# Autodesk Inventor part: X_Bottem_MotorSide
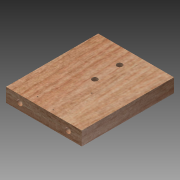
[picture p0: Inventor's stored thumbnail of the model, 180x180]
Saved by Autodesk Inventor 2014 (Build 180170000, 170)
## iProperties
Created: 2013-12
Part Number: X_Bottem_MotorSide
Material: Birch
Document SubType Name: Modeling
Designer: Bram
Density: 0.512 g/cm^3
Appearance: Birch - Natural Medium Gloss
Author: Bram
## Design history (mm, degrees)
sketch "Sketch1"
  geometry: L1 (0, 0)-(110, 0); L2 (110, 0)-(110, 20); L3 (110, 20)-(0, 20); L4 (0, 20)-(0, 0)
  constraints: 8 end point, 2 parallel, 1 horizontal, 1 perpendicular
  dimensions: "d0" = 110 distance of L3.end L2.end; "d1" = 20 distance of L2.end L1.end
extrude "Extrusion1" new body sketch "Sketch1" distance "d2" = 134; taper "d3" = 0 deg
sketch "Sketch2"
  geometry: L1 (0, -20)-(0, 0) reference; L2 (0, -10)-(-20, -10); L3 (-20, -10)-(-90, -10); C1 r 4 at (-90, -10); C2 r 4 at (-20, -10)
  constraints: 4 end point, 2 centre point, 2 coincident, 1 collinear, 1 midpoint, 1 perpendicular
  dimensions: "d4" = 20 distance of L2.start L2.end; "d5" = 70 distance of L2.end L3.end; "d6" = 8 diameter of C1; "d7" = 8 diameter of C2
extrude "Extrusion2" cut sketch "Sketch2" distance "d8" = 134; taper "d9" = 0 deg
sketch "Sketch3"
  geometry: L1 (0, 134)-(110, 134) reference; L2 (0, 0)-(0, 134) reference; L3 (55, 134)-(55, 110); L4 (55, 110)-(55, 74); C1 r 4 at (55, 74); C2 r 4 at (55, 110)
  constraints: 4 end point, 2 centre point, 2 coincident, 1 collinear, 1 midpoint, 1 parallel
  dimensions: "d10" = 24 distance of L3.start L3.end; "d11" = 36 distance of L3.end L4.end; "d12" = 8 diameter of C1; "d13" = 8 diameter of C2
extrude "Extrusion3" cut sketch "Sketch3" distance "d14" = 134; taper "d15" = 0 deg
body "Solid1"
